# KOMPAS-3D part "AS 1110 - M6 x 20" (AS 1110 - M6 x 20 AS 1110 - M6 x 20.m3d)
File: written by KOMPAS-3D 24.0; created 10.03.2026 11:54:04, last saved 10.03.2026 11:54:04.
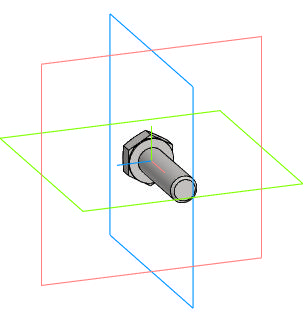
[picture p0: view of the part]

Document properties: Автор: R2D2; Полное имя файла: E:\Работа\Зайцев\BV3232P(4pc)-FP-3WL-F-ISO-H Кран шаровой DN.ru Ду15-100 Ру16\DN20\исходные материалы\AS 1110 - M6 x 20 AS 1110 - M6 x 20.m3d

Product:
- Body: Solid1  | qty 1
- Part/product: AS 1110 - M6 x 20
    Комментарий: Болты и винты   шестигранные точные   метрические ISO
    additional columns: Сталь, мягкая

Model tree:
1. Solid1  (labels: Solid1)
